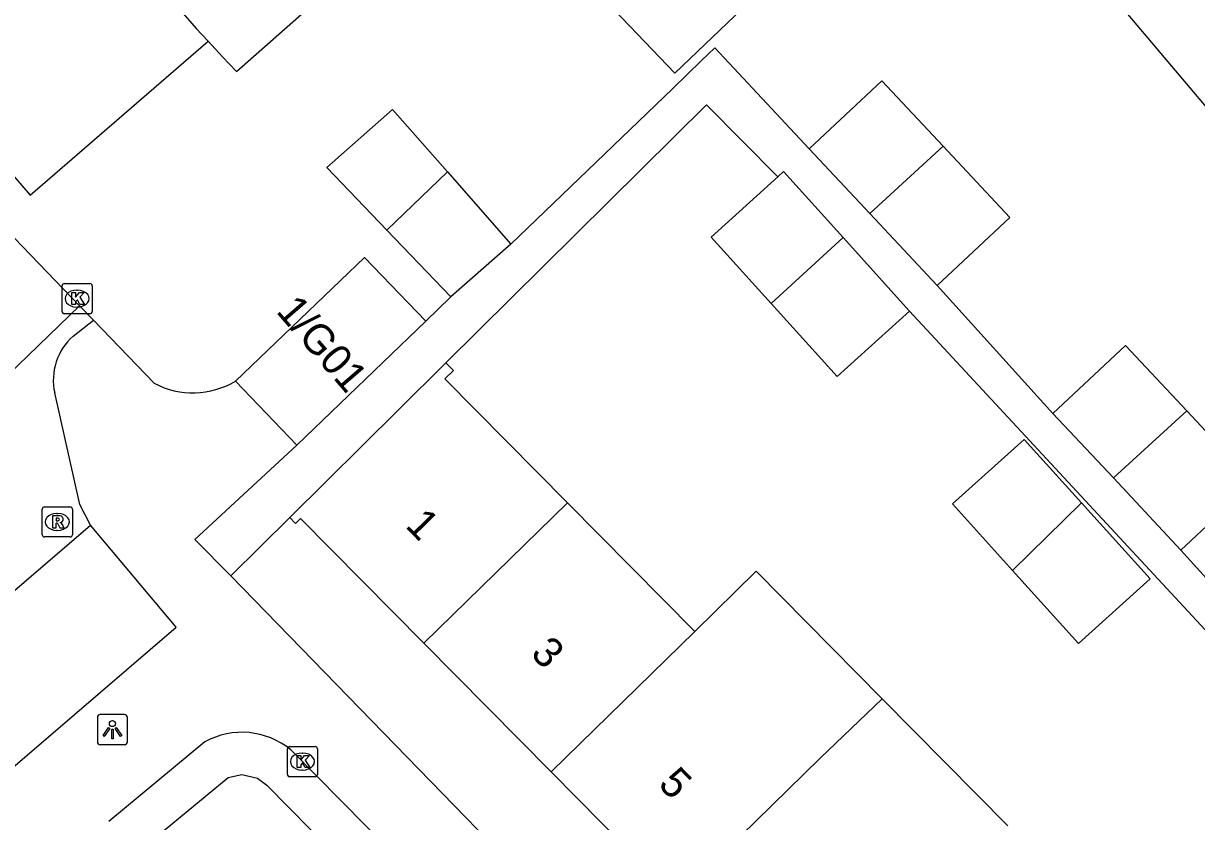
# Model space of a CAD drawing. Extents: x 157466 to 158888, y 383063 to 384677.
# Drawn here: x 158031.44 to 158070.38, y 383652.61 to 383679.09 of the extents above; entities that cross this region are included whole.
import ezdxf

# ---------------------------------------------------------------- set-up
doc = ezdxf.new("R2010")
doc.units = 0
for name, color, linetype in [('IMGEO_Groenvoorziening', 7, 'Continuous'), ('IMGEO_Kolk', 7, 'Continuous'), ('IMGEO_Lichtpunt', 7, 'Continuous'), ('IMGEO_Pand', 7, 'Continuous'), ('IMGEO_Pand_nummerreeks', 7, 'Continuous'), ('IMGEO_Parkeervlak_open', 7, 'Continuous'), ('IMGEO_Rijbaan_lokaal_open', 7, 'Continuous'), ('IMGEO_Rioolput', 7, 'Continuous'), ('IMGEO_Voetpad_open', 7, 'Continuous')]:
    doc.layers.add(name, color=color, linetype=linetype)

msp = doc.modelspace()

# ---------------------------------------------------------------- linework, layer by layer
at = {"layer": 'IMGEO_Groenvoorziening'}
msp.add_lwpolyline([(158041.313, 383643.097), (158035.288, 383650.263), (158035.13, 383650.957), (158035.277, 383651.587), (158036.146, 383652.348), (158038.233, 383654.076), (158038.69, 383654.173), (158039.207, 383654.051), (158039.517, 383653.821), (158046.118, 383647.117)], dxfattribs=at)
at = {"layer": 'IMGEO_Kolk'}
for p, q in [((158032.72, 383669.532), (158032.72, 383670.384)), ((158032.795, 383670.458), (158033.647, 383670.458)), ((158033.208, 383670.238), (158033.233, 383670.238)), ((158033.721, 383670.384), (158033.721, 383669.532)), ((158033.647, 383669.458), (158032.795, 383669.458)), ((158033.231, 383669.678), (158033.206, 383669.678)), ((158040.198, 383654.173), (158040.198, 383655.025)), ((158040.273, 383655.099), (158041.125, 383655.099)), ((158041.199, 383655.025), (158041.199, 383654.173)), ((158040.686, 383654.879), (158040.711, 383654.879)), ((158040.709, 383654.319), (158040.684, 383654.319)), ((158041.125, 383654.099), (158040.273, 383654.099))]:
    msp.add_line(p, q, dxfattribs=at)
for points in [[(158032.72, 383669.532), (158032.72, 383670.384)], [(158032.795, 383670.458), (158033.647, 383670.458)], [(158033.041, 383670.158), (158033.164, 383670.158), (158033.164, 383670.007), (158033.294, 383670.158), (158033.458, 383670.158), (158033.312, 383670.007), (158033.465, 383669.758), (158033.313, 383669.758), (158033.228, 383669.922), (158033.164, 383669.855), (158033.164, 383669.758), (158033.041, 383669.758), (158033.041, 383670.158)], [(158033.721, 383670.384), (158033.721, 383669.532)], [(158033.647, 383669.458), (158032.795, 383669.458)], [(158040.198, 383654.173), (158040.198, 383655.025)], [(158040.273, 383655.099), (158041.125, 383655.099)], [(158041.199, 383655.025), (158041.199, 383654.173)], [(158040.519, 383654.799), (158040.642, 383654.799), (158040.642, 383654.648), (158040.772, 383654.799), (158040.936, 383654.799), (158040.79, 383654.648), (158040.943, 383654.399), (158040.791, 383654.399), (158040.706, 383654.563), (158040.642, 383654.496), (158040.642, 383654.399), (158040.519, 383654.399), (158040.519, 383654.799)], [(158041.125, 383654.099), (158040.273, 383654.099)]]:
    msp.add_lwpolyline(points, dxfattribs=at)
for centre, start, end in [((158032.797, 383670.382), 91.552, 178.448), ((158032.797, 383670.382), 91.552, 178.448), ((158033.645, 383670.382), 1.552, 88.448), ((158033.645, 383670.382), 1.552, 88.448), ((158032.797, 383669.534), 181.552, 268.448), ((158032.797, 383669.534), 181.552, 268.448), ((158033.645, 383669.534), 271.552, 358.448), ((158033.645, 383669.534), 271.552, 358.448), ((158040.275, 383655.023), 91.552, 178.448), ((158040.275, 383655.023), 91.552, 178.448), ((158041.123, 383655.023), 1.552, 88.448), ((158041.123, 383655.023), 1.552, 88.448), ((158040.275, 383654.175), 181.552, 268.448), ((158040.275, 383654.175), 181.552, 268.448), ((158041.123, 383654.175), 271.552, 358.448), ((158041.123, 383654.175), 271.552, 358.448)]:
    msp.add_arc(centre, 0.0765, start, end, dxfattribs=at)
for centre, major_axis, ratio, start_param, end_param in [((158033.207, 383669.958), (-0.387, 0.002), 0.722429, 4.712389, 7.853982), ((158033.232, 383669.958), (-0.39, 0.002), 0.717154, 1.570796, 4.712389), ((158040.685, 383654.599), (-0.387, 0.002), 0.722429, 4.712389, 7.853982), ((158040.71, 383654.599), (-0.39, 0.002), 0.717154, 1.570796, 4.712389)]:
    msp.add_ellipse(centre, major_axis=major_axis, ratio=ratio, start_param=start_param, end_param=end_param, dxfattribs=at)
at = {"layer": 'IMGEO_Lichtpunt'}
for p, q in [((158034.794, 383656.157), (158033.986, 383656.157)), ((158034.794, 383656.157), (158033.986, 383656.157)), ((158033.892, 383656.062), (158033.892, 383655.255)), ((158033.892, 383656.062), (158033.892, 383655.255)), ((158034.888, 383655.255), (158034.888, 383656.062)), ((158034.888, 383655.255), (158034.888, 383656.062)), ((158033.986, 383655.161), (158034.794, 383655.161)), ((158033.986, 383655.161), (158034.794, 383655.161))]:
    msp.add_line(p, q, dxfattribs=at)
for points in [[(158034.266, 383655.726), (158034.305, 383655.698), (158034.117, 383655.436), (158034.079, 383655.463), (158034.266, 383655.726)], [(158034.368, 383655.678), (158034.415, 383655.678), (158034.415, 383655.356), (158034.368, 383655.356), (158034.368, 383655.678)], [(158034.478, 383655.698), (158034.516, 383655.725), (158034.703, 383655.463), (158034.664, 383655.435), (158034.478, 383655.698)]]:
    msp.add_lwpolyline(points, dxfattribs=at)
msp.add_circle((158034.391, 383655.86), 0.0994, dxfattribs=at)
for centre, start, end in [((158033.986, 383656.062), 90, 180), ((158033.986, 383656.062), 90, 180), ((158034.794, 383656.062), 0, 90), ((158034.794, 383656.062), 0, 90), ((158033.986, 383655.255), 180, 270), ((158033.986, 383655.255), 180, 270), ((158034.794, 383655.255), 270, 0), ((158034.794, 383655.255), 270, 360)]:
    msp.add_arc(centre, 0.0946, start, end, dxfattribs=at)
at = {"layer": 'IMGEO_Pand'}
for points in [[(158031.569, 383685.38), (158027.267, 383681.66), (158027.02, 383681.945), (158026.766, 383681.725), (158030.495, 383677.414), (158029.171, 383676.269), (158031.662, 383673.388), (158037.565, 383678.493)], [(158031.569, 383685.38), (158037.168, 383678.915), (158037.565, 383678.493)], [(158037.565, 383678.493), (158038.046, 383677.983), (158038.509, 383677.491), (158042.999, 383681.46), (158042.69, 383681.771)], [(158072.726, 383677.258), (158071.078, 383675.88), (158067.259, 383680.398), (158068.897, 383681.783)], [(158053.274, 383681.653), (158055.291, 383679.571), (158053.065, 383677.434), (158051.058, 383679.524)], [(158057.524, 383674.927), (158059.934, 383677.184), (158061.964, 383675.014)], [(158043.5, 383672.232), (158041.506, 383674.307), (158043.69, 383676.229), (158045.509, 383674.162)], [(158059.528, 383672.786), (158057.524, 383674.927)], [(158061.964, 383675.014), (158059.528, 383672.786)], [(158061.964, 383675.014), (158064.179, 383672.648), (158061.769, 383670.392)], [(158043.5, 383672.232), (158045.509, 383674.162)], [(158045.509, 383674.162), (158047.618, 383671.765)], [(158056.257, 383669.792), (158054.262, 383672.001), (158056.476, 383673.999)], [(158058.65, 383671.981), (158056.67, 383674.174), (158056.476, 383673.999)], [(158061.769, 383670.392), (158059.528, 383672.786)], [(158045.63, 383670.016), (158043.5, 383672.232)], [(158047.618, 383671.765), (158045.63, 383670.016)], [(158056.257, 383669.792), (158058.65, 383671.981)], [(158058.65, 383671.981), (158060.851, 383669.543)], [(158044.792, 383669.205), (158042.755, 383671.327), (158038.475, 383667.221)], [(158060.851, 383669.543), (158058.444, 383667.369), (158056.257, 383669.792)], [(158040.512, 383665.098), (158044.792, 383669.205)], [(158065.611, 383666.151), (158068.021, 383668.408), (158070.052, 383666.237)], [(158045.464, 383667.826), (158043.876, 383666.255), (158040.276, 383662.692)], [(158045.464, 383667.826), (158045.71, 383667.578), (158045.427, 383667.298), (158049.497, 383663.186)], [(158038.475, 383667.221), (158040.512, 383665.098)], [(158067.616, 383664.009), (158070.052, 383666.237)], [(158070.052, 383666.237), (158072.266, 383663.872), (158069.856, 383661.616)], [(158067.616, 383664.009), (158065.611, 383666.151)], [(158064.27, 383660.943), (158062.282, 383663.145), (158064.658, 383665.289), (158066.561, 383663.181)], [(158069.856, 383661.616), (158067.616, 383664.009)], [(158044.729, 383658.528), (158049.497, 383663.186)], [(158049.497, 383663.186), (158053.719, 383658.92)], [(158066.561, 383663.181), (158068.84, 383660.658), (158066.464, 383658.513), (158064.27, 383660.943)], [(158066.561, 383663.181), (158064.27, 383660.943)], [(158044.729, 383658.528), (158040.633, 383662.667), (158040.465, 383662.5), (158040.276, 383662.692)], [(158053.719, 383658.92), (158055.759, 383660.913), (158059.947, 383656.682)], [(158053.719, 383658.92), (158048.951, 383654.263)], [(158048.951, 383654.263), (158044.729, 383658.528)], [(158053.12, 383650.05), (158057.888, 383654.708), (158059.947, 383656.682)], [(158059.947, 383656.682), (158064.119, 383652.466)], [(158053.12, 383650.05), (158048.951, 383654.263)]]:
    msp.add_lwpolyline(points, dxfattribs=at)
at = {"layer": 'IMGEO_Parkeervlak_open'}
msp.add_lwpolyline([(158033.301, 383669.722), (158028.432, 383674.777), (158026.297, 383677.24), (158022.137, 383681.981)], dxfattribs=at)
at = {"layer": 'IMGEO_Rijbaan_lokaal_open'}
for points in [[(158033.301, 383669.722), (158029.537, 383666.096), (158018.338, 383678.57)], [(158033.765, 383669.24), (158033.301, 383669.722)], [(158033.091, 383668.717), (158033.765, 383669.24)], [(158033.765, 383669.24), (158035.779, 383667.149)], [(158033.669, 383662.438), (158033.315, 383663.131), (158032.477, 383666.829)], [(158040.512, 383665.098), (158037.131, 383661.964), (158038.32, 383660.756)], [(158027.75, 383657.373), (158033.669, 383662.438)], [(158027.75, 383657.373), (158030.605, 383654.01), (158036.509, 383659.061), (158033.669, 383662.438)], [(158038.32, 383660.756), (158062.095, 383636.318)], [(158037.462, 383655.255), (158034.269, 383652.611)], [(158053.697, 383641.436), (158040.31, 383654.991)]]:
    msp.add_lwpolyline(points, dxfattribs=at)
for centre, radius, start, end in [((158034.375, 383667.255), 1.946, 131.3077, 192.662), ((158037.063, 383669.582), 2.751, 242.1817, 300.8779), ((158038.692, 383653.027), 2.544, 50.5072, 118.9009)]:
    msp.add_arc(centre, radius, start, end, dxfattribs=at)
at = {"layer": 'IMGEO_Rioolput'}
for p, q in [((158032.061, 383662.124), (158032.061, 383662.976)), ((158032.136, 383663.05), (158032.988, 383663.05)), ((158032.549, 383662.83), (158032.574, 383662.83)), ((158033.062, 383662.976), (158033.062, 383662.124)), ((158032.988, 383662.05), (158032.136, 383662.05)), ((158032.572, 383662.27), (158032.547, 383662.27))]:
    msp.add_line(p, q, dxfattribs=at)
for points in [[(158032.061, 383662.124), (158032.061, 383662.976)], [(158032.136, 383663.05), (158032.988, 383663.05)], [(158032.65, 383662.748), (158032.398, 383662.75), (158032.398, 383662.35)], [(158033.062, 383662.976), (158033.062, 383662.124)], [(158032.398, 383662.35), (158032.522, 383662.35), (158032.522, 383662.512), (158032.533, 383662.512)], [(158032.576, 383662.669), (158032.522, 383662.669), (158032.522, 383662.588)], [(158032.522, 383662.588), (158032.574, 383662.588)], [(158032.58, 383662.483), (158032.651, 383662.35), (158032.791, 383662.35), (158032.726, 383662.476)], [(158032.988, 383662.05), (158032.136, 383662.05)]]:
    msp.add_lwpolyline(points, dxfattribs=at)
for centre, radius, start, end in [((158032.138, 383662.974), 0.0765, 91.552, 178.448), ((158032.138, 383662.974), 0.0765, 91.552, 178.448), ((158032.649, 383662.638), 0.109, 350.3612, 89.416), ((158032.986, 383662.974), 0.0765, 1.552, 88.448), ((158032.986, 383662.974), 0.0765, 1.552, 88.448), ((158032.532, 383662.459), 0.0533, 26.0293, 88.6989), ((158032.558, 383662.777), 0.19, 274.7715, 282.9687), ((158032.582, 383662.573), 0.0964, 77.0061, 93.1865), ((158032.596, 383662.63), 0.0378, 276.6634, 79.6772), ((158032.647, 383662.638), 0.112, 277.5842, 350.9817), ((158032.631, 383662.423), 0.108, 29.5134, 73.7905), ((158032.138, 383662.126), 0.0765, 181.552, 268.448), ((158032.138, 383662.126), 0.0765, 181.552, 268.448), ((158032.986, 383662.126), 0.0765, 271.552, 358.448), ((158032.986, 383662.126), 0.0765, 271.552, 358.448)]:
    msp.add_arc(centre, radius, start, end, dxfattribs=at)
for centre, major_axis, ratio, start_param, end_param in [((158032.548, 383662.55), (-0.387, 0.002), 0.722429, 4.712389, 7.853982), ((158032.573, 383662.55), (-0.39, 0.002), 0.717154, 1.570796, 4.712389)]:
    msp.add_ellipse(centre, major_axis=major_axis, ratio=ratio, start_param=start_param, end_param=end_param, dxfattribs=at)
at = {"layer": 'IMGEO_Voetpad_open'}
for points in [[(158047.618, 383671.765), (158052.992, 383676.931), (158053.948, 383677.856), (158054.386, 383678.28), (158057.524, 383674.927)], [(158056.476, 383673.999), (158054.116, 383676.385), (158045.464, 383667.826)], [(158061.769, 383670.392), (158065.611, 383666.151)], [(158044.792, 383669.205), (158045.63, 383670.016)], [(158072.945, 383656.515), (158060.851, 383669.543)], [(158040.276, 383662.692), (158038.32, 383660.756)], [(158069.856, 383661.616), (158073.799, 383657.268)]]:
    msp.add_lwpolyline(points, dxfattribs=at)

# ---------------------------------------------------------------- texts
at = {"layer": 'IMGEO_Pand_nummerreeks'}
for s, rotation, p in [('1/G01', 310.8151, (158039.797, 383669.524)), ('1', 314.328, (158044.083, 383662.4)), ('3', 314.328, (158048.238, 383658.147)), ('5', 314.328, (158052.472, 383653.813))]:
    msp.add_text(s, height=1, rotation=rotation, dxfattribs=at).set_placement(p)

doc.saveas('drawing.dxf')
